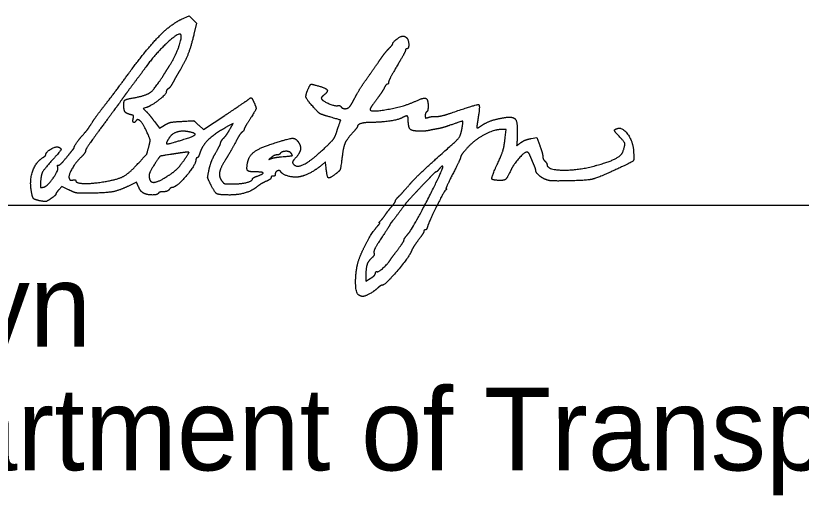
# Model space of a CAD drawing. Extents: x 0 to 34, y 0 to 22.
# Drawn here: x 25.704 to 27.036, y 7.199 to 8.012 of the extents above; entities that cross this region are included whole.
import ezdxf

# ---------------------------------------------------------------- set-up
doc = ezdxf.new("R2010")
doc.units = 0
doc.layers.add('SH_Data', color=7, linetype='Continuous')
doc.layers.add('SH_Text', color=7, linetype='Continuous')

msp = doc.modelspace()

# ---------------------------------------------------------------- linework, layer by layer
at = {"layer": 'SH_Data'}
msp.add_line((24.5, 7.691), (28, 7.691), dxfattribs=at)
at = {"layer": 'SH_Text'}
for points in [[(25.9853, 8.0062), (25.9979, 8.012), (26.0042, 8.0057), (26.0106, 7.9993), (26.0062, 7.9806)], [(25.9253, 7.8562), (25.9203, 7.8546), (25.9255, 7.8495)], [(25.9392, 7.8328), (25.9477, 7.8213), (25.9565, 7.8265)], [(26.0143, 7.8265), (26.0224, 7.8189), (26.0587, 7.843)], [(26.0682, 7.8212), (26.0726, 7.8292), (26.0671, 7.8263)], [(26.534, 7.8053), (26.5355, 7.8191), (26.5277, 7.8191)], [(26.5779, 7.8037), (26.5876, 7.8053), (26.5926, 7.7917)], [(26.23, 7.7576), (26.2293, 7.7644), (26.2234, 7.7593)], [(25.9123, 7.722), (25.909, 7.73), (25.8951, 7.7231)], [(25.7937, 7.7169), (25.7822, 7.7227), (25.7771, 7.7169)], [(26.2977, 7.5714), (26.2977, 7.5621), (26.3052, 7.5664)]]:
    msp.add_lwpolyline(points, dxfattribs=at)
for points in [[(25.8957, 7.9143), (25.9254, 7.9549), (25.9672, 7.9978), (25.9853, 8.0062)], [(25.9838, 7.9804), (25.9802, 7.984), (25.9416, 7.9483), (25.9262, 7.927)], [(25.9655, 7.9283), (25.9749, 7.9432), (25.9869, 7.9773), (25.9838, 7.9804)], [(26.0062, 7.9806), (26.0012, 7.9595), (25.992, 7.9359), (25.9826, 7.9199)], [(26.3433, 7.9643), (26.3433, 7.9671), (26.3565, 7.9774), (26.3602, 7.9775)], [(26.3602, 7.9775), (26.3623, 7.9775), (26.3652, 7.9762), (26.3668, 7.9747)], [(26.3668, 7.9747), (26.3703, 7.9712), (26.3707, 7.9559), (26.3673, 7.9559)], [(26.3229, 7.9389), (26.3269, 7.9448), (26.3331, 7.9525), (26.3367, 7.9562)], [(26.3367, 7.9562), (26.3403, 7.9598), (26.3433, 7.9634), (26.3433, 7.9643)], [(26.3649, 7.9534), (26.3649, 7.952), (26.3584, 7.9399), (26.3505, 7.9266)], [(26.3673, 7.9559), (26.366, 7.9559), (26.3649, 7.9548), (26.3649, 7.9534)], [(26.3013, 7.9079), (26.3092, 7.9192), (26.319, 7.9331), (26.3229, 7.9389)], [(25.9262, 7.927), (25.9226, 7.9221), (25.9132, 7.9094), (25.9053, 7.8989)], [(25.955, 7.9117), (25.9583, 7.9169), (25.963, 7.9244), (25.9655, 7.9283)], [(26.3505, 7.9266), (26.3426, 7.9132), (26.3361, 7.9008), (26.3361, 7.8991)], [(25.8555, 7.8609), (25.8644, 7.8722), (25.8825, 7.8963), (25.8957, 7.9143)], [(25.9826, 7.9199), (25.9791, 7.914), (25.9739, 7.9048), (25.971, 7.8995)], [(25.9053, 7.8989), (25.8974, 7.8884), (25.8893, 7.8774), (25.8873, 7.8745)], [(25.9052, 7.873), (25.9258, 7.8768), (25.9398, 7.8877), (25.955, 7.9117)], [(25.971, 7.8995), (25.9682, 7.8943), (25.9644, 7.8891), (25.9626, 7.888)], [(26.2799, 7.8743), (26.2837, 7.8816), (26.2933, 7.8967), (26.3013, 7.9079)], [(26.3361, 7.8991), (26.3361, 7.8973), (26.3352, 7.8959), (26.3341, 7.8959)], [(25.9626, 7.888), (25.9608, 7.887), (25.9593, 7.8845), (25.9593, 7.8826)], [(26.209, 7.8568), (26.1975, 7.8698), (26.1953, 7.8766), (26.1992, 7.8862)], [(26.1992, 7.8862), (26.203, 7.8952), (26.2061, 7.8963), (26.2188, 7.8925)], [(26.2188, 7.8925), (26.2308, 7.889), (26.2337, 7.8828), (26.226, 7.8769)], [(26.3288, 7.8893), (26.3271, 7.8857), (26.3209, 7.8766), (26.3152, 7.8691)], [(26.3341, 7.8959), (26.333, 7.8959), (26.3306, 7.893), (26.3288, 7.8893)], [(25.8873, 7.8745), (25.8853, 7.8715), (25.87, 7.8506), (25.8532, 7.8279)], [(25.8873, 7.8609), (25.8873, 7.8677), (25.8914, 7.8705), (25.9052, 7.873)], [(25.9593, 7.8826), (25.9593, 7.8788), (25.9335, 7.8588), (25.9253, 7.8562)], [(26.0978, 7.8695), (26.1023, 7.8733), (26.1047, 7.8724), (26.1077, 7.8658)], [(26.226, 7.8769), (26.2233, 7.8749), (26.2218, 7.872), (26.2228, 7.8707)], [(26.2706, 7.8581), (26.2719, 7.8598), (26.2761, 7.8671), (26.2799, 7.8743)], [(26.3825, 7.8673), (26.3955, 7.8735), (26.4033, 7.8703), (26.4033, 7.8589)], [(25.834, 7.8315), (25.837, 7.8363), (25.8467, 7.8495), (25.8555, 7.8609)], [(25.8983, 7.8445), (25.8911, 7.8463), (25.8873, 7.852), (25.8873, 7.8609)], [(26.0587, 7.843), (26.0786, 7.8563), (26.0962, 7.8682), (26.0978, 7.8695)], [(26.1077, 7.8658), (26.1121, 7.8562), (26.1111, 7.8521), (26.1009, 7.8362)], [(26.2228, 7.8707), (26.2254, 7.8669), (26.2453, 7.8587), (26.25, 7.8595)], [(26.25, 7.8595), (26.2522, 7.8599), (26.2548, 7.859), (26.2556, 7.8577)], [(26.3152, 7.8691), (26.3096, 7.8617), (26.3049, 7.8544), (26.3049, 7.8531)], [(26.3049, 7.8531), (26.3049, 7.8478), (26.3645, 7.8587), (26.3825, 7.8673)], [(26.4033, 7.8589), (26.4033, 7.8544), (26.4022, 7.85), (26.4009, 7.8491)], [(26.4456, 7.8482), (26.486, 7.8621), (26.4919, 7.8605), (26.4878, 7.8366)], [(25.9255, 7.8495), (25.9283, 7.8467), (25.9345, 7.8392), (25.9392, 7.8328)], [(26.2325, 7.8416), (26.2217, 7.8447), (26.2168, 7.8479), (26.209, 7.8568)], [(26.2556, 7.8577), (26.2578, 7.8542), (26.2678, 7.8545), (26.2706, 7.8581)], [(26.4009, 7.8491), (26.3996, 7.8483), (26.3985, 7.8455), (26.3985, 7.8428)], [(26.4168, 7.8412), (26.421, 7.841), (26.4339, 7.8442), (26.4456, 7.8482)], [(25.9034, 7.8382), (25.9043, 7.8418), (25.9031, 7.8433), (25.8983, 7.8445)], [(25.9077, 7.8335), (25.9052, 7.8296), (25.902, 7.8331), (25.9034, 7.8382)], [(25.9265, 7.8149), (25.9203, 7.8285), (25.9106, 7.8382), (25.9077, 7.8335)], [(25.9565, 7.8265), (25.963, 7.8304), (25.9706, 7.8321), (25.9857, 7.8329)], [(25.9857, 7.8329), (26.006, 7.8341), (26.0062, 7.8341), (26.0143, 7.8265)], [(26.1009, 7.8362), (26.0956, 7.8281), (26.0913, 7.8205), (26.0913, 7.8194)], [(26.2493, 7.8179), (26.255, 7.8347), (26.2546, 7.8353), (26.2325, 7.8416)], [(26.3583, 7.8385), (26.3527, 7.8355), (26.3225, 7.8311), (26.3075, 7.8311)], [(26.3697, 7.8338), (26.3697, 7.8411), (26.366, 7.8427), (26.3583, 7.8385)], [(26.389, 7.8162), (26.3766, 7.8162), (26.3697, 7.8225), (26.3697, 7.8338)], [(26.3985, 7.8428), (26.3985, 7.8389), (26.3995, 7.8383), (26.4039, 7.8397)], [(26.4039, 7.8397), (26.4069, 7.8407), (26.4127, 7.8413), (26.4168, 7.8412)], [(26.4609, 7.8216), (26.463, 7.8331), (26.4613, 7.8335), (26.4403, 7.8262)], [(26.4878, 7.8366), (26.4865, 7.829), (26.4857, 7.8224), (26.4862, 7.8219)], [(26.4938, 7.8257), (26.501, 7.8308), (26.5192, 7.8371), (26.5329, 7.8393)], [(26.5329, 7.8393), (26.5476, 7.8416), (26.5552, 7.8311), (26.5544, 7.8099)], [(25.8177, 7.8096), (25.8243, 7.8169), (25.8285, 7.8227), (25.834, 7.8315)], [(25.8532, 7.8279), (25.8364, 7.8053), (25.8226, 7.7851), (25.8225, 7.7831)], [(26.0671, 7.8263), (26.0437, 7.8137), (26.021, 7.793), (26.0168, 7.7806)], [(26.0554, 7.8031), (26.0608, 7.8091), (26.0633, 7.8127), (26.0682, 7.8212)], [(26.0913, 7.8194), (26.0913, 7.8182), (26.0897, 7.816), (26.0877, 7.8144)], [(26.2833, 7.824), (26.2833, 7.8231), (26.2791, 7.8177), (26.2739, 7.8119)], [(26.3075, 7.8311), (26.296, 7.8311), (26.2833, 7.8274), (26.2833, 7.824)], [(26.4189, 7.8202), (26.4149, 7.8195), (26.409, 7.8184), (26.4057, 7.8176)], [(26.4161, 7.7686), (26.4516, 7.8002), (26.4585, 7.8083), (26.4609, 7.8216)], [(26.4403, 7.8262), (26.4325, 7.8235), (26.4229, 7.8208), (26.4189, 7.8202)], [(26.5277, 7.8191), (26.515, 7.8191), (26.4812, 7.8007), (26.4691, 7.7872)], [(26.4862, 7.8219), (26.4867, 7.8214), (26.4901, 7.8231), (26.4938, 7.8257)], [(26.7245, 7.8105), (26.7192, 7.8162), (26.719, 7.8189), (26.7236, 7.8206)], [(26.7236, 7.8206), (26.7322, 7.8239), (26.7506, 7.799), (26.7516, 7.7827)], [(25.8033, 7.7891), (25.8033, 7.7908), (25.8124, 7.8038), (25.8177, 7.8096)], [(25.9298, 7.7903), (25.9323, 7.8002), (25.932, 7.8024), (25.9265, 7.8149)], [(25.9649, 7.8057), (25.9579, 7.795), (25.9625, 7.7942), (25.9869, 7.8017)], [(25.9975, 7.8152), (25.9866, 7.8174), (25.9693, 7.8123), (25.9649, 7.8057)], [(25.9869, 7.8017), (26.0061, 7.8076), (26.0101, 7.8127), (25.9975, 7.8152)], [(26.0877, 7.8144), (26.0858, 7.8128), (26.0827, 7.8086), (26.0809, 7.8051)], [(26.231, 7.7906), (26.2414, 7.8006), (26.2455, 7.8068), (26.2493, 7.8179)], [(26.2739, 7.8119), (26.2655, 7.8024), (26.2597, 7.7899), (26.2581, 7.7771)], [(26.4057, 7.8176), (26.4024, 7.8168), (26.3949, 7.8162), (26.389, 7.8162)], [(26.5544, 7.8099), (26.5537, 7.7915), (26.5536, 7.7918), (26.5613, 7.7973)], [(26.7336, 7.7814), (26.7376, 7.7932), (26.736, 7.7981), (26.7245, 7.8105)], [(26.0429, 7.779), (26.0473, 7.7867), (26.0512, 7.7943), (26.0514, 7.7961)], [(26.0514, 7.7961), (26.0517, 7.7978), (26.0535, 7.801), (26.0554, 7.8031)], [(26.0809, 7.8051), (26.0727, 7.7897), (26.0649, 7.7759), (26.0588, 7.7662)], [(26.0971, 7.7623), (26.0992, 7.7736), (26.1154, 7.787), (26.1347, 7.7934)], [(26.1347, 7.7934), (26.1665, 7.804), (26.1799, 7.8044), (26.185, 7.7949)], [(26.185, 7.7949), (26.1882, 7.7889), (26.1848, 7.7775), (26.1774, 7.7696)], [(26.5194, 7.7575), (26.5284, 7.7774), (26.5324, 7.7906), (26.534, 7.8053)], [(26.5613, 7.7973), (26.5651, 7.8), (26.5726, 7.8029), (26.5779, 7.8037)], [(25.7553, 7.7771), (25.7554, 7.7809), (25.7721, 7.7908), (25.7759, 7.7894)], [(25.7759, 7.7894), (25.7819, 7.7871), (25.7796, 7.7822), (25.7653, 7.7663)], [(25.7888, 7.7699), (25.7941, 7.7765), (25.7996, 7.7832), (25.8009, 7.7848)], [(25.8009, 7.7848), (25.8022, 7.7864), (25.8033, 7.7884), (25.8033, 7.7891)], [(25.8225, 7.7831), (25.8224, 7.7812), (25.8191, 7.7763), (25.8151, 7.7724)], [(25.9101, 7.7598), (25.9262, 7.7774), (25.9265, 7.7779), (25.9298, 7.7903)], [(25.9851, 7.7796), (25.9795, 7.7787), (25.9717, 7.7775), (25.9677, 7.7769)], [(25.9901, 7.7679), (25.9979, 7.7793), (25.997, 7.7814), (25.9851, 7.7796)], [(26.0168, 7.7806), (26.0151, 7.7754), (26.0128, 7.7711), (26.0117, 7.7711)], [(26.032, 7.7512), (26.0336, 7.7589), (26.0385, 7.7714), (26.0429, 7.779)], [(26.1708, 7.7792), (26.168, 7.7825), (26.1546, 7.7817), (26.1523, 7.7781)], [(26.1549, 7.7728), (26.1716, 7.7743), (26.174, 7.7753), (26.1708, 7.7792)], [(26.174, 7.7617), (26.1793, 7.7531), (26.2061, 7.7666), (26.231, 7.7906)], [(26.4691, 7.7872), (26.4632, 7.7807), (26.4585, 7.7741), (26.4585, 7.7726)], [(26.5709, 7.7807), (26.5666, 7.7807), (26.5483, 7.7602), (26.5436, 7.7501)], [(26.5765, 7.7741), (26.575, 7.7778), (26.5725, 7.7807), (26.5709, 7.7807)], [(26.5926, 7.7917), (26.5954, 7.7843), (26.5977, 7.7761), (26.5977, 7.7736)], [(26.6847, 7.7571), (26.7084, 7.7634), (26.7314, 7.7748), (26.7336, 7.7814)], [(26.7516, 7.7827), (26.7526, 7.7674), (26.7499, 7.7643), (26.7265, 7.7533)], [(25.7304, 7.7155), (25.7275, 7.734), (25.7382, 7.764), (25.7506, 7.7718)], [(25.7653, 7.7663), (25.7516, 7.7511), (25.7466, 7.741), (25.746, 7.7272)], [(25.7506, 7.7718), (25.7532, 7.7734), (25.7553, 7.7758), (25.7553, 7.7771)], [(25.7765, 7.7586), (25.7779, 7.7583), (25.7834, 7.7633), (25.7888, 7.7699)], [(25.8151, 7.7724), (25.8053, 7.7628), (25.7929, 7.7407), (25.7947, 7.736)], [(25.9677, 7.7769), (25.9499, 7.7743), (25.9479, 7.7732), (25.9406, 7.762)], [(25.9602, 7.7392), (25.9714, 7.7462), (25.9824, 7.7567), (25.9901, 7.7679)], [(26.0097, 7.7681), (26.0095, 7.7596), (25.9764, 7.7207), (25.9693, 7.7207)], [(26.0117, 7.7711), (26.0106, 7.7711), (26.0097, 7.7698), (26.0097, 7.7681)], [(26.0588, 7.7662), (26.0508, 7.7536), (26.0486, 7.7384), (26.0537, 7.7316)], [(26.138, 7.7721), (26.1334, 7.7684), (26.1334, 7.7684), (26.1381, 7.77)], [(26.1468, 7.7759), (26.1445, 7.7759), (26.1405, 7.7742), (26.138, 7.7721)], [(26.1381, 7.77), (26.1407, 7.771), (26.1483, 7.7722), (26.1549, 7.7728)], [(26.1523, 7.7781), (26.1516, 7.7769), (26.1491, 7.7759), (26.1468, 7.7759)], [(26.1774, 7.7696), (26.1746, 7.7667), (26.1731, 7.7631), (26.174, 7.7617)], [(26.2581, 7.7771), (26.2553, 7.7546), (26.2536, 7.7492), (26.2479, 7.7447)], [(26.372, 7.7259), (26.3792, 7.7343), (26.399, 7.7535), (26.4161, 7.7686)], [(26.4585, 7.7726), (26.4585, 7.771), (26.4525, 7.7581), (26.4453, 7.744)], [(26.5824, 7.76), (26.5806, 7.7641), (26.578, 7.7705), (26.5765, 7.7741)], [(26.5977, 7.7736), (26.5977, 7.7711), (26.5993, 7.7675), (26.6013, 7.7655)], [(25.7509, 7.7212), (25.7572, 7.7221), (25.7773, 7.7505), (25.7753, 7.7557)], [(25.7753, 7.7557), (25.7745, 7.7577), (25.7751, 7.759), (25.7765, 7.7586)], [(25.8536, 7.7305), (25.8763, 7.7342), (25.8959, 7.7444), (25.9101, 7.7598)], [(25.9406, 7.762), (25.9324, 7.7493), (25.9292, 7.7395), (25.9315, 7.7337)], [(26.1106, 7.7471), (26.0991, 7.7471), (26.0951, 7.7517), (26.0971, 7.7623)], [(26.2234, 7.7593), (26.214, 7.7511), (26.194, 7.7405), (26.1849, 7.7388)], [(26.2479, 7.7447), (26.2362, 7.7355), (26.2318, 7.7386), (26.23, 7.7576)], [(26.3694, 7.6421), (26.3771, 7.6508), (26.4303, 7.7545), (26.4282, 7.7566)], [(26.4225, 7.7525), (26.4201, 7.7496), (26.4175, 7.7471), (26.4167, 7.7471)], [(26.4282, 7.7566), (26.4275, 7.7573), (26.4249, 7.7555), (26.4225, 7.7525)], [(26.5267, 7.7327), (26.5122, 7.7327), (26.5106, 7.7382), (26.5194, 7.7575)], [(26.5858, 7.7504), (26.5857, 7.7515), (26.5842, 7.7558), (26.5824, 7.76)], [(26.6013, 7.7655), (26.6033, 7.7635), (26.6049, 7.7608), (26.6049, 7.7595)], [(26.6049, 7.7595), (26.6049, 7.7509), (26.6555, 7.7495), (26.6847, 7.7571)], [(26.7265, 7.7533), (26.6917, 7.737), (26.6707, 7.7322), (26.6313, 7.7318)], [(25.9315, 7.7337), (25.9335, 7.7284), (25.9471, 7.731), (25.9602, 7.7392)], [(26.034, 7.7272), (26.0296, 7.7363), (26.0294, 7.7385), (26.032, 7.7512)], [(26.1057, 7.7354), (26.1057, 7.7364), (26.1094, 7.7386), (26.114, 7.7402)], [(26.114, 7.7402), (26.1243, 7.7439), (26.1227, 7.7471), (26.1106, 7.7471)], [(26.1405, 7.7399), (26.1385, 7.7399), (26.1369, 7.7388), (26.1369, 7.7375)], [(26.1441, 7.7433), (26.1441, 7.7414), (26.1425, 7.7399), (26.1405, 7.7399)], [(26.1536, 7.7473), (26.1516, 7.7506), (26.1441, 7.7474), (26.1441, 7.7433)], [(26.1849, 7.7388), (26.1763, 7.7372), (26.1565, 7.7426), (26.1536, 7.7473)], [(26.4079, 7.7393), (26.4038, 7.735), (26.3933, 7.724), (26.3845, 7.7147)], [(26.4167, 7.7471), (26.416, 7.7471), (26.412, 7.7436), (26.4079, 7.7393)], [(26.4453, 7.744), (26.438, 7.7299), (26.4329, 7.7183), (26.4339, 7.7183)], [(26.5436, 7.7501), (26.5379, 7.7377), (26.5331, 7.7327), (26.5267, 7.7327)], [(26.6014, 7.7348), (26.5944, 7.7381), (26.5859, 7.7465), (26.5858, 7.7504)], [(25.746, 7.7272), (25.7458, 7.7216), (25.7466, 7.7205), (25.7509, 7.7212)], [(25.7947, 7.736), (25.7956, 7.7336), (25.7979, 7.7327), (25.8009, 7.7334)], [(25.8009, 7.7334), (25.8035, 7.7341), (25.8057, 7.7338), (25.8057, 7.7327)], [(25.8057, 7.7327), (25.8057, 7.7281), (25.8313, 7.7269), (25.8536, 7.7305)], [(26.0658, 7.708), (26.0483, 7.7081), (26.0413, 7.7123), (26.034, 7.7272)], [(26.0537, 7.7316), (26.0566, 7.7277), (26.0601, 7.7268), (26.0713, 7.7268)], [(26.0713, 7.7268), (26.0853, 7.7267), (26.1057, 7.7318), (26.1057, 7.7354)], [(26.1315, 7.7326), (26.1242, 7.7293), (26.1165, 7.7247), (26.1123, 7.7212)], [(26.1369, 7.7375), (26.1369, 7.7361), (26.1345, 7.7339), (26.1315, 7.7326)], [(26.3535, 7.7055), (26.3565, 7.7083), (26.3648, 7.7175), (26.372, 7.7259)], [(26.6313, 7.7318), (26.6164, 7.7316), (26.6061, 7.7326), (26.6014, 7.7348)], [(25.747, 7.6978), (25.7361, 7.6998), (25.7323, 7.7039), (25.7304, 7.7155)], [(25.7771, 7.7169), (25.7744, 7.7137), (25.7721, 7.7103), (25.7721, 7.7093)], [(25.8245, 7.7111), (25.8089, 7.7111), (25.803, 7.7122), (25.7937, 7.7169)], [(25.8951, 7.7231), (25.8796, 7.7154), (25.8544, 7.7111), (25.8245, 7.7111)], [(25.9205, 7.7113), (25.9179, 7.7128), (25.9142, 7.7175), (25.9123, 7.722)], [(25.9543, 7.7135), (25.9506, 7.7135), (25.9469, 7.7125), (25.9461, 7.7111)], [(25.9641, 7.7171), (25.9625, 7.7152), (25.9581, 7.7135), (25.9543, 7.7135)], [(25.9693, 7.7207), (25.9681, 7.7207), (25.9657, 7.7191), (25.9641, 7.7171)], [(26.1123, 7.7212), (26.1046, 7.7149), (26.0803, 7.7079), (26.0658, 7.708)], [(26.3845, 7.7147), (26.3757, 7.7054), (26.3658, 7.6942), (26.3625, 7.6897)], [(26.4331, 7.7165), (26.4304, 7.7147), (26.4052, 7.6637), (26.4022, 7.6541)], [(26.4339, 7.7183), (26.4349, 7.7183), (26.4345, 7.7175), (26.4331, 7.7165)], [(25.7637, 7.7019), (25.7572, 7.6974), (25.7536, 7.6965), (25.747, 7.6978)], [(25.7721, 7.7093), (25.7721, 7.7083), (25.7683, 7.705), (25.7637, 7.7019)], [(25.9461, 7.7111), (25.9441, 7.7079), (25.9266, 7.7081), (25.9205, 7.7113)], [(26.3481, 7.6983), (26.3482, 7.6994), (26.3506, 7.7027), (26.3535, 7.7055)], [(26.3313, 7.6751), (26.3333, 7.6782), (26.3379, 7.6842), (26.3415, 7.6884)], [(26.3625, 7.6897), (26.3544, 7.6788), (26.3439, 7.665), (26.3409, 7.6614)], [(26.3415, 7.6884), (26.3451, 7.6927), (26.3481, 7.6971), (26.3481, 7.6983)], [(26.3235, 7.6651), (26.3258, 7.6676), (26.3293, 7.6721), (26.3313, 7.6751)], [(26.3176, 7.6553), (26.3203, 7.6583), (26.3218, 7.6607), (26.3209, 7.6607)], [(26.3209, 7.6607), (26.32, 7.6607), (26.3212, 7.6627), (26.3235, 7.6651)], [(26.3409, 7.6614), (26.3396, 7.6598), (26.3385, 7.6581), (26.3385, 7.6576)], [(26.2875, 7.6027), (26.2934, 7.6176), (26.3105, 7.6475), (26.3176, 7.6553)], [(26.3385, 7.6576), (26.3385, 7.657), (26.3322, 7.6471), (26.3244, 7.6354)], [(26.3961, 7.6462), (26.3961, 7.6449), (26.3918, 7.6381), (26.3866, 7.6312)], [(26.3983, 7.6487), (26.3971, 7.6487), (26.3961, 7.6476), (26.3961, 7.6462)], [(26.4022, 7.6541), (26.4013, 7.6512), (26.3996, 7.6487), (26.3983, 7.6487)], [(26.3244, 7.6354), (26.3158, 7.6224), (26.3108, 7.6126), (26.3115, 7.6099)], [(26.3625, 7.6318), (26.3625, 7.6331), (26.3656, 7.6377), (26.3694, 7.6421)], [(26.3523, 7.6159), (26.3579, 7.6233), (26.3625, 7.6304), (26.3625, 7.6318)], [(26.3866, 7.6312), (26.3814, 7.6243), (26.3763, 7.6163), (26.3752, 7.6135)], [(26.3115, 7.6099), (26.3122, 7.6074), (26.3106, 7.6038), (26.3078, 7.6013)], [(26.3752, 7.6135), (26.3716, 7.6036), (26.3304, 7.5551), (26.3257, 7.5551)], [(26.3397, 7.5987), (26.341, 7.6008), (26.3467, 7.6086), (26.3523, 7.6159)], [(26.2857, 7.5383), (26.2798, 7.5421), (26.281, 7.5864), (26.2875, 7.6027)], [(26.3078, 7.6013), (26.3019, 7.5961), (26.2977, 7.5838), (26.2977, 7.5714)], [(26.3169, 7.5779), (26.3188, 7.5768), (26.3355, 7.5919), (26.3397, 7.5987)], [(26.3052, 7.5664), (26.3094, 7.5688), (26.3133, 7.5726), (26.3139, 7.5749)], [(26.3139, 7.5749), (26.3145, 7.5772), (26.3159, 7.5786), (26.3169, 7.5779)], [(26.3257, 7.5551), (26.3243, 7.5551), (26.321, 7.5531), (26.3183, 7.5506)], [(26.3183, 7.5506), (26.3121, 7.5449), (26.2961, 7.5359), (26.2922, 7.536)], [(26.2922, 7.536), (26.2906, 7.536), (26.2877, 7.537), (26.2857, 7.5383)]]:
    msp.add_open_spline(points, degree=2, dxfattribs=at)

# ---------------------------------------------------------------- texts
for s, p in [('Pamela Boratyn', (24.5, 7.451)), ('Director, Department of Transportation', (24.5, 7.241))]:
    msp.add_text(s, height=0.14, dxfattribs=at).set_placement(p)

doc.saveas('drawing.dxf')
